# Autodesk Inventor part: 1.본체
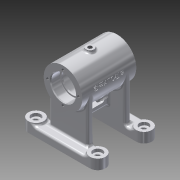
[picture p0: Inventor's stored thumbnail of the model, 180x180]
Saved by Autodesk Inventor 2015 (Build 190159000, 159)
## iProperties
Created: 2015-11
Part Number: 1.본체
Material: 알루미늄 6061
Document SubType Name: Modeling
Designer: Administrator
Density: 2.7 g/cm^3
Appearance: 알루미늄 - 평지
Mass: 357.092 g
Surface Area: 455.979 cm^2
Volume: 132.256 cm^3
Author: Administrator
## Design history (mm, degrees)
sketch "스케치1"
  geometry: C1 r 25 at (0, 0); 1 further point
  constraints: 1 centre point, 1 coincident
  dimensions: "d1" = 50 diameter of C1
extrude "돌출1" new body sketch "스케치1" distance "d2" = 70; taper "d3" = 0 deg
sketch "스케치2"
  geometry: L1 (25, 70)-(-25, 70) reference; L2 (-25, 0)-(25, 0) reference; L3 (0, 0)-(-16, 0); L4 (-25, 0)-(25, 0) reference; L5 (-16, 0)-(-16, 12); L6 (-14, 14)-(-18, 14); L7 (-21, 17)-(-21, 35); L8 (-25, 0)-(-25, 70) reference; L9 (-16, 70)-(-16, 58); L10 (-15, 56)-(-18, 56); L11 (-21, 53)-(-21, 35); L12 (-16, 70)-(0, 70); L13 (25, 70)-(-25, 70) reference; L14 (0, 70)-(0, 0); L15 (-14, 58)-(-14, 56); L16 (-14, 56)-(-15, 56); L17 (-16, 58)-(-14, 58); L18 (-16, 12)-(-14, 12); L19 (-14, 12)-(-14, 14); A1 r 3 centre (-18, 17) between (-21, 17) and (-18, 14); A2 r 3 centre (-18, 53) between (-18, 56) and (-21, 53)
  constraints: 28 end point, 4 point on circle, 4 tangent, 3 horizontal, 3 perpendicular, 2 centre point, 2 vertical, 1 equal radius, 1 midpoint, 1 point on line
revolve "회전1" sketch "스케치2" stored, may be unused: angle "d14" = 90 deg
chamfer "모따기1" distance "d15" = 1; stored, may be unused: second distance "d16" = 2, angle "d17" = 45 deg
sketch "스케치3"
  geometry: C1 r 25 at (0, 0) reference; C2 r 17 at (0, 0) reference; 5 further points
hole "구멍1" sketch "스케치3" at (0, 20), (20, 0), (0, -20), (-20, 0) diameter "d19" = 3.242; stored, may be unused: countersink angle "d23" = 82 deg, drill point angle "d25" = 118 deg; dims "d20" = 8, "d21" = 19.05, "d22" = 4.775, "d24" = 10
node "작업 평면1"
node "작업 평면2"
sketch "스케치4"
  geometry: L1 (25, 70)-(-25, 70) reference; L2 (-25, 0)-(25, 0) reference; L3 (-25, 0)-(-25, 70) reference; C1 r 5 at (0, 35); 1 further point
  constraints: 1 centre point
  dimensions: "d28" = 10 diameter of C1
extrude "돌출2" join sketch "스케치4" stored distance "d29" = 70; taper "d30" = 0 deg
sketch "스케치5"
  geometry: C1 r 5 at (0, 0) reference; 2 further points
  constraints: 1 coincident
  node "투영된 루프4"
fillet "모깎기1" dims "d38" = 0.3, "d39" = 3
sketch "스케치6"
  geometry: L1 (14.618, -20.281)-(16.372, -22.715); L2 (19.058, -16.18)-(21.239, -19.207); L3 (21.239, -19.207)-(16.372, -22.715); A1 r 25 centre (0, 0) between (19.058, -16.18) and (14.618, -20.281) reference; A2 r 25 centre (0, 0) between (14.618, -20.281) and (19.058, -16.18); 1 further point
  constraints: 6 end point, 4 point on circle, 1 centre point, 1 concentric, 1 parallel
  dimensions: "d42" = 6 distance between parallel lines of L1 L2
revolve "회전2" sketch "스케치6" stored, may be unused: angle "d43" = 90 deg
sketch "스케치7"
  geometry: C1 r 6 at (0, 0) reference; 2 further points
  constraints: 1 coincident
hole "구멍3" sketch "스케치7" at (0, 0) diameter "d44" = 5.188; stored, may be unused: countersink angle "d48" = 82 deg, drill point angle "d50" = 118 deg; dims "d45" = 15, "d46" = 19.05, "d47" = 4.775, "d49" = 19
fillet "모깎기2" dims "d51" = 3
node "작업 평면3"
sketch "스케치9"
  geometry: L1 (-25, 0)-(25, 0) reference; L2 (-25, 0)-(-25, 70) reference; L3 (25, 0)-(25, 70) reference; L4 (25, 70)-(-25, 70) reference; L5 (0, -5)-(40, -5); L6 (40, -5)-(40, 5); L7 (0, -5)-(-40, -5); L8 (-40, -5)-(-40, 5); L9 (40, 15)-(-40, 15); L10 (25, 35)-(-25, 35); L11 (40, 55)-(-40, 55); L12 (0, 75)-(40, 75); L13 (40, 75)-(40, 65); L14 (0, 75)-(-40, 75); L15 (-40, 75)-(-40, 65); A1 r 10 centre (40, 5) between (40, -5) and (40, 15); A2 r 10 centre (-40, 5) between (-40, -5) and (-40, 15); A3 r 10 centre (40, 65) between (40, 75) and (40, 55); A4 r 10 centre (-40, 65) between (-40, 75) and (-40, 55); 1 further point
  constraints: 22 end point, 9 symmetric about line, 8 point on circle, 4 centre point, 4 coincident, 2 midpoint, 2 perpendicular, 1 horizontal, 1 tangent, 2 other
  dimensions: "d61" = 40 distance of L5.start L5.end; "d62" = 10 distance of L5.end L6.end; "d63" = 40 distance of L5.start L7.end; "d64" = 10 distance of L7.end L8.end
extrude "돌출3" join sketch "스케치9" distance "d65" = 13; taper "d66" = 0 deg
sketch "스케치10"
  geometry: L1 (40, 5)-(-40, 5) reference; L2 (-40, -15)-(40, -15) reference; L3 (-40, -75)-(40, -75) reference; L4 (40, -55)-(-40, -55) reference; A1 r 10 centre (-40, -5) between (-40, 5) and (-40, -15) reference; A2 r 10 centre (40, -5) between (40, -15) and (40, 5) reference; A3 r 10 centre (40, -65) between (40, -75) and (40, -55) reference; A4 r 10 centre (-40, -65) between (-40, -55) and (-40, -75) reference; 5 further points
  constraints: 4 coincident
hole "구멍4" sketch "스케치10" at (-40, -5), (-40, -65), (40, -65), (40, -5) diameter "d67" = 12; stored, may be unused: countersink angle "d71" = 90 deg, drill point angle "d73" = 0 deg; dims "d68" = 6, "d69" = 4, "d70" = 2, "d72" = 4
sketch "스케치11"
  geometry: C1 r 6 at (0, 0) reference; C2 r 6 at (80, 0) reference; C3 r 6 at (80, -60) reference; C4 r 6 at (0, -60) reference; 5 further points
  constraints: 4 coincident
hole "구멍5" sketch "스케치11" at (0, 0), (0, -60), (80, -60), (80, 0) diameter "d74" = 6; stored, may be unused: countersink angle "d78" = 90 deg, drill point angle "d80" = 0 deg; dims "d75" = 6, "d76" = 7, "d77" = 2, "d79" = 9
fillet "모깎기3" dims "d81" = 0.3
sketch "스케치12"
  geometry: L1 (-40, -15)-(40, -15) reference; L2 (40, -55)-(-40, -55) reference; L3 (-25, 0)-(-25, -70) reference; L4 (25, 0)-(25, -70) reference; L5 (-25, -15)-(-25, -7); L6 (-25, -7)-(25, -7); L7 (25, -7)-(25, -15); L8 (25, -15)-(-25, -15); L9 (-25, -55)-(-25, -63); L10 (-25, -63)-(25, -63); L11 (25, -63)-(25, -55); L12 (25, -55)-(-25, -55); 1 further point
  constraints: 16 end point, 12 point on line, 2 collinear, 2 perpendicular
  dimensions: "d82" = 8 distance of L5.start L5.end; "d83" = 8 distance of L9.start L9.end
extrude "돌출4" join sketch "스케치12" stored distance "d84" = 13; taper "d85" = 0 deg
sketch "스케치13"
  geometry: L1 (-55, 55)-(0, 55) reference; L2 (-25, 0)-(-25, 70) reference; L3 (-55, 15)-(0, 15) reference; L4 (-45, 35)-(-45, 55); L5 (-45, 35)-(-45, 15); L6 (-25, 35)-(-25, 55); L7 (-25, 55)-(-45, 55); L8 (-25, 35)-(-25, 15); L9 (-25, 15)-(-45, 15); L10 (-68, 91)-(-68, -21) reference; L11 (-31.5, 23.5)-(-31.5, 46.5); L12 (-38.5, 46.5)-(-38.5, 23.5); L13 (0, 15)-(-25, 15) reference; L14 (-25, 55)-(-22.648, 55); L15 (-55, 55)-(0, 55) reference; L16 (-22.648, 55)-(-22.648, 15); L17 (-22.648, 15)-(-25, 15); L18 (-31.5, 46.5)-(-31.5, 23.5); L19 (-38.5, 23.5)-(-38.5, 46.5); L20 (-45, 15)-(-45, 55); L21 (-22.648, 55)-(-22.648, 15); A1 r 3.5 centre (-35, 46.5) between (-31.5, 46.5) and (-38.5, 46.5); A2 r 3.5 centre (-35, 23.5) between (-38.5, 23.5) and (-31.5, 23.5); A3 r 3.5 centre (-35, 23.5) between (-38.5, 23.5) and (-31.5, 23.5); A4 r 3.5 centre (-35, 46.5) between (-31.5, 46.5) and (-38.5, 46.5); 1 further point
  constraints: 30 end point, 8 point on circle, 8 point on line, 6 collinear, 4 centre point, 4 perpendicular, 3 tangent, 2 coincident, 1 midpoint, 1 vertical
sketch "스케치14"
  geometry: L1 (40, 5)-(-40, 5) reference; L2 (-40, -15)-(40, -15) reference; L3 (-40, -75)-(40, -75) reference; L4 (40, -55)-(-40, -55) reference; L5 (-25, -15)-(-25, -7) reference; L6 (-25, -7)-(25, -7) reference; L7 (25, -7)-(25, -15) reference; L8 (25, -55)-(25, -63) reference; L9 (25, -63)-(-25, -63) reference; L10 (-25, -63)-(-25, -55) reference; L11 (40, 5)-(-40, 5) reference; L12 (-40, 5)-(40, 5); L13 (-40, -15)-(-25, -15); L14 (-40, -15)-(40, -15) reference; L15 (-25, -7)-(-25, -15); L16 (-25, -7)-(25, -7); L17 (25, -7)-(25, -15); L18 (25, -15)-(40, -15); L19 (-40, -55)-(-25, -55); L20 (-25, -55)-(-25, -63); L21 (-25, -63)-(25, -63); L22 (25, -63)-(25, -55); L23 (25, -55)-(40, -55); L24 (40, -55)-(-40, -55) reference; L25 (40, -75)-(-40, -75); C1 r 3 at (-40, -5) reference; C2 r 3 at (40, -5) reference; C3 r 3 at (40, -65) reference; C4 r 3 at (-40, -65) reference; A1 r 10 centre (-40, -5) between (-40, 5) and (-40, -15) reference; A2 r 10 centre (40, -5) between (40, -15) and (40, 5) reference; A3 r 10 centre (40, -65) between (40, -75) and (40, -55) reference; A4 r 10 centre (-40, -65) between (-40, -55) and (-40, -75) reference; A5 r 10 centre (-40, -5) between (-40, -15) and (-40, 5) reference; A6 r 10 centre (40, -5) between (40, 5) and (40, -15) reference; A7 r 10 centre (40, -65) between (40, -55) and (40, -75) reference; A8 r 10 centre (-40, -65) between (-40, -75) and (-40, -55) reference; A9 r 10 centre (-40, -5) between (-40, -15) and (-40, 5); A10 r 10 centre (40, -5) between (40, 5) and (40, -15); A11 r 10 centre (-40, -65) between (-40, -75) and (-40, -55); A12 r 10 centre (40, -65) between (40, -55) and (40, -75); 1 further point
  constraints: 26 end point, 10 collinear, 10 point on circle, 5 tangent, 4 centre point, 3 concentric, 2 coincident, 2 point on line, 1 horizontal
extrude "돌출6" cut sketch "스케치14" distance "d93" = 3; taper "d94" = 0 deg
fillet "모깎기4" dims "d95" = 3
fillet "모깎기5" dims "d96" = 3
fillet "모깎기6" dims "d97" = 3
extrude "돌출7" join sketch "스케치13" stored distance "d98" = 8; taper "d99" = 0 deg
extrude "돌출8" cut sketch "스케치13" stored distance "d100" = 8; taper "d101" = 0 deg
fillet "모깎기7" dims "d102" = 3
fillet "모깎기8" dims "d103" = 3
node "작업 평면4"
sketch "스케치15"
  geometry: L1 (28, 40)-(28, 30) reference; L2 (25, 70)-(-25, 70) reference; 2 further points
  constraints: 1 other
feature "엠보싱1" sketch "스케치15" dims "d1" = 50, "d105" = 0.5, "d106" = 0
sketch "스케치16"
  geometry: 1 further point
hole "구멍6" sketch "스케치5" diameter "d107" = 5.188; stored, may be unused: countersink angle "d111" = 90 deg, drill point angle "d113" = 118 deg; dims "d108" = 12, "d109" = 4, "d110" = 2, "d112" = 16
node "솔리드1"
mirror "대칭1"
node "투영된 루프1"
node "투영된 루프2"
node "투영된 루프3"
node "투영된 루프5"
node "투영된 루프6"
node "투영된 루프7"
node "투영된 루프8"
node "투영된 루프9"
node "투영된 루프10"
node "투영된 루프11"
node "투영된 루프12"
node "투영된 루프13"
other parameters: "d26" = 35, "d27" = 28, "d57" = -96
